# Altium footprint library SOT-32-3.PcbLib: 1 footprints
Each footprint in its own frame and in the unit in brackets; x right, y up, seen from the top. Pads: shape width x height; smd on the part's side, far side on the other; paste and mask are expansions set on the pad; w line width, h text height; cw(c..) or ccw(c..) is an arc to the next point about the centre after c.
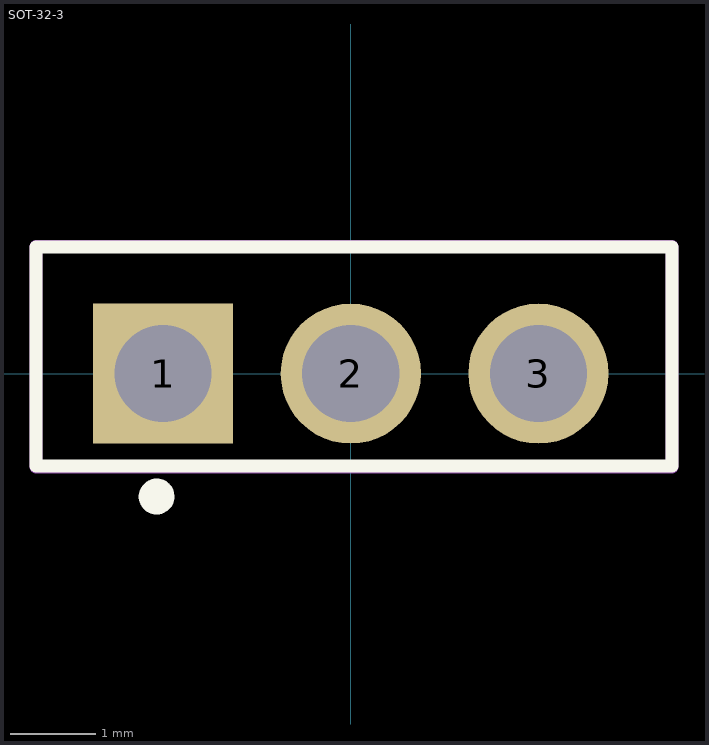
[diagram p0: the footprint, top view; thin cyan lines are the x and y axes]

## SOT-32-3 [mil]
pads (3):
  rect 65x65 hole 45: 1(-87.01,0)
  round 65 hole 45: 2(0,0) 3(87.01,0)
Top Overlay:
  lines w6: -145.98,-42.8 -145.98,58.67 148.83,58.67 148.83,-42.8 -145.98,-42.8
  lines w11.81: -87.77,-56.1 ccw(c-90,-57) -87.59,-57
Mechanical 15:
  lines w6: -146,-43.23 -146,59 149,59 149,-43.23 -146,-43.23
3D body "User Library-TO-126 (SOT32) Gold PCB.step": height 519.29, standoff -139.37, extent -148.88,-38.6 150.33,61.79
